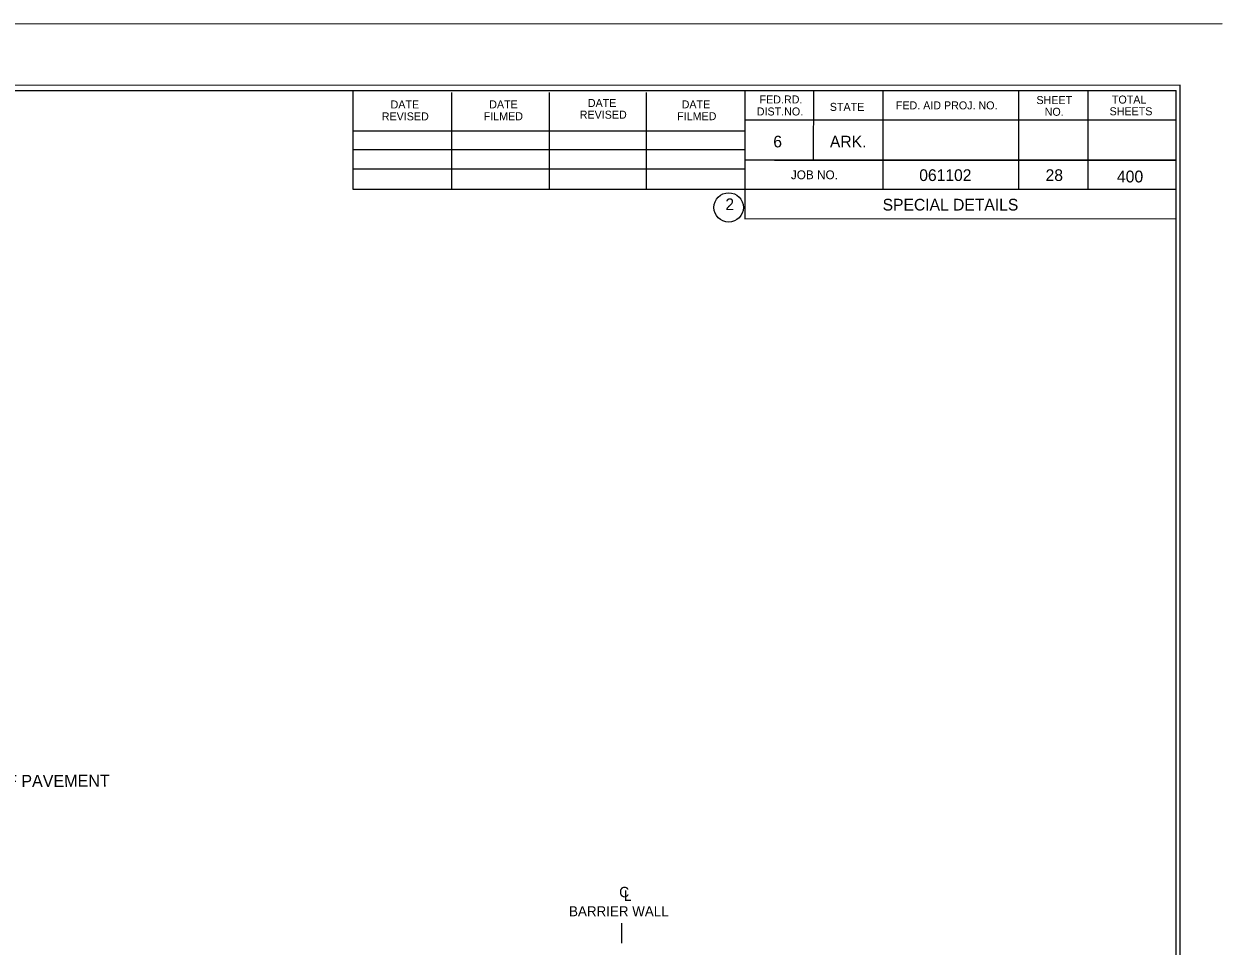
# Model space of a CAD drawing. Extents: x 714919 to 718439, y 1619644 to 1621844.
# Drawn here: x 717241 to 718439, y 1620922 to 1621844 of the extents above; entities that cross this region are included whole.
import ezdxf

# ---------------------------------------------------------------- set-up
doc = ezdxf.new("R2010")
doc.units = 0
for name, color, linetype in [('R_Border', 7, 'Continuous'), ('R_Border Notes', 7, 'Continuous'), ('R_Centerline', 7, 'Continuous'), ('R_No Plot', 7, 'Continuous')]:
    doc.layers.add(name, color=color, linetype=linetype)

msp = doc.modelspace()

# ---------------------------------------------------------------- linework, layer by layer
at = {"layer": 'R_Border'}
for p, q in [((718438.8, 1621843.9), (714918.8, 1621843.6)), ((715231.1, 1621777.2), (718392.9, 1621777.2)), ((717570.2, 1621678.4), (717570.3, 1621777.3)), ((717668.7, 1621678.4), (717668.9, 1621775.3)), ((717766.4, 1621678.3), (717766.4, 1621775.3)), ((717863.3, 1621678.4), (717863.3, 1621775.2)), ((717961.6, 1621777.2), (717961.8, 1621649.2)), ((718030.3, 1621777.1), (718030.2, 1621707.8)), ((718099.6, 1621777.2), (718099.6, 1621678.5)), ((718235.3, 1621777.3), (718235.3, 1621678.6)), ((718304.8, 1621777.4), (718304.8, 1621678.4)), ((718393, 1619722.6), (718392.9, 1621777.2)), ((718392.8, 1621747.6), (717961.9, 1621747.7)), ((718392.9, 1621748), (718392.9, 1621748)), ((717570.1, 1621737), (717961.7, 1621737)), ((717570.2, 1621718.4), (717961.7, 1621718.4)), ((718392.9, 1621707.8), (717961.8, 1621707.8)), ((717991.4, 1621707.8), (718392.9, 1621707.8)), ((717570.2, 1621678.4), (717570.2, 1621699.1)), ((717570.2, 1621699.1), (717961.9, 1621699.1)), ((718392.9, 1621678.4), (717570.2, 1621678.4)), ((717961.8, 1621649.2), (718392.9, 1621649.3))]:
    msp.add_line(p, q, dxfattribs=at)
msp.add_circle((717945.6, 1621660.5), 14.7, dxfattribs=at)
at = {"layer": 'R_Centerline'}
msp.add_line((717838.4, 1620945.1), (717838.4, 1620925.3), dxfattribs=at)
at = {"layer": 'R_No Plot'}
msp.add_lwpolyline([(715227, 1619717.4), (718396.9, 1619717.5), (718397, 1621782.6), (715226.9, 1621782.4)], close=True, dxfattribs=at)

# ---------------------------------------------------------------- texts
at = {"layer": 'R_Border'}
for s, height, rotation, p in [('DATE', 8, 0.0017, (717607.6, 1621759.4)), ('DATE', 8, 0.0017, (717706.2, 1621759.5)), ('DATE', 8, 0.0017, (717804.8, 1621760.9)), ('DATE', 8, 0.0017, (717898.6, 1621759.5)), ('FED.RD.', 8, 0.0017, (717976.5, 1621764.4)), ('STATE', 8, 0.0017, (718046.7, 1621757)), ('FED. AID PROJ. NO.', 8, 0.0017, (718112.7, 1621758.5)), ('SHEET', 8, 0.0017, (718253.3, 1621763.8)), ('TOTAL', 8, 0.0017, (718328.7, 1621764.3)), ('REVISED', 8, 0.0017, (717598.8, 1621747.5)), ('FILMED', 8, 0.0017, (717700.7, 1621747.6)), ('REVISED', 8, 0.0017, (717796.7, 1621749.2)), ('FILMED', 8, 0.0017, (717894.1, 1621747.7)), ('DIST.NO.', 8, 0.0017, (717973.7, 1621752.4)), ('NO.', 8, 0.0017, (718261.5, 1621752.1)), ('SHEETS', 8, 0.0017, (718326.4, 1621752.6)), ('6', 11.7, 0.0017, (717990.2, 1621720.5)), ('ARK.', 11.72, 0.0017, (718046.8, 1621720.4)), ('JOB NO.', 8.79, 0.0017, (718007.8, 1621688.7)), ('061102', 11.7, 0.0018, (718136.1, 1621686.9)), ('28', 11.7, 0.0018, (718262.4, 1621686.9)), ('400', 11.79, 0.0018, (718333.7, 1621685.5)), ('2', 11.7, 0.0017, (717942.3, 1621657.8)), ('SPECIAL DETAILS', 11.7, 0.0018, (718099.5, 1621657.4))]:
    msp.add_text(s, height=height, rotation=rotation, dxfattribs=at).set_placement(p)
at = {"layer": 'R_Border Notes'}
msp.add_text('TOP OF PAVEMENT', height=12, rotation=0.1435, dxfattribs=at).set_placement((717174.3, 1621081.1))
at = {"layer": 'R_Centerline'}
for s, height, p in [('C', 10.4, (717836.1, 1620971)), ('L', 10.4, (717840.8, 1620967.4)), ('BARRIER WALL', 10, (717786, 1620952))]:
    msp.add_text(s, height=height, dxfattribs=at).set_placement(p)

doc.saveas('drawing.dxf')
